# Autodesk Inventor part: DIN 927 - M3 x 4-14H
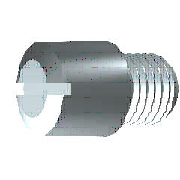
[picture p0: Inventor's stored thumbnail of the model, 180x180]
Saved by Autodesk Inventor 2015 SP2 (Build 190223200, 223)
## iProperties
IsCustomPart: 0
Created: 2012-02
Part Number: DIN 927 - M3 x 4-14H
Material: Stahl, weich
Description: Passschraube kopflos
Document SubType Name: Modeling
Standard: DIN 927
Designer: rYan
Standards Organization: DIN
Language: de-DE
Size Designation: M3 x 4-14H
Categories: <MemberInstance><Categories><Category DisplayName="Verbindungselemente" InternalName="e4da775c-781d-43d5-af7c-5136215cf5a6" Mnemonic="FSTN"><Category DisplayNam
Density: 7.85 g/cm^3
Mass: 0.616547 g
Surface Area: 1.17401 cm^2
Volume: 0.0785411 cm^3
Appearance: Halbpoliert
Author: rYan
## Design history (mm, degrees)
body "Solid1"
sketch "Skizze1"
  geometry: L1 (0, 0)-(8.5, 0); L2 (8.5, 0)-(8.5, 1.5); L3 (8.5, 1.5)-(4, 1.5); L4 (4, 1.5)-(4, 2); L5 (4, 2)-(0, 2); L6 (0, 2)-(0, 0); L7 (-1.7, 0)-(10.2, 0) reference; L8 (0, -0.4)-(0, 2.4) reference; A1 r 0.5 centre (4.25, 1.933) between (4, 1.5) and (4.5, 1.5)
  constraints: 12 end point, 4 parallel, 2 collinear, 2 point on circle, 1 centre point, 1 horizontal, 1 perpendicular, 1 point on line
  dimensions: "d0" = 4 distance between parallel lines of L4 L6 (= KOH); "d1" = 4.5 distance between parallel lines of L2 L4 (= GEL); "d2" = 3 diameter of L3 L1 (= NND); "d3" = 4 diameter of L5 L1 (= KOD); "d14" = 0.5 distance of A1.end L3.end (= SBR); "d15" = 0.5 radius of A1 (= SBR)
revolve "Körper" stored, may be unused: angle "d4" = 90 deg
sketch "Skizze2"
  geometry: L1 (0, -2.8)-(0, 2.8) reference; L2 (-2.8, 0)-(2.8, 0) reference; L3 (-2, 0.25)-(2, 0.25); L4 (2, 0.25)-(2, -0.25); L5 (2, -0.25)-(-2, -0.25); L6 (-2, -0.25)-(-2, 0.25); L7 (-2, 0)-(2, 0); L8 (0, 0.25)-(0, -0.25); C1 r 2 at (0, 0) reference
  constraints: 12 end point, 4 midpoint, 2 collinear, 2 parallel, 1 horizontal, 1 perpendicular, 1 tangent
  dimensions: "d5" = 0.5 distance between parallel lines of L3 L5 (= SBR)
extrude "Loch" cut sketch "Skizze2" distance "d6" = 0.8 (= STI); taper "d7" = 0 deg
chamfer "Fase1" distance "d8" = 0.5 (= PHH); stored, may be unused: angle "d9" = 45 deg, second distance "d19" = 0.5 (= PHH)
feature "Gewinde" dims "d10" = 4.5 (= GEL), "d11" = 0
chamfer "Fase2" distance "d12" = 0.30673 (= -0.5 x GD1 + 0.5 x NND); stored, may be unused: second distance "d13" = 0.30673 (= GUL), angle "d20" = 45 deg
revolve "Nut1" stored, may be unused: angle "d16" = 90 deg
workplane "Work Plane1"
other parameters: "NND" = 3 [user parameter; used in 2 equation terms], "GEL" = 4.5 [user parameter; used in 3 equation terms], "KOD" = 4 [user parameter; used in 1 equation term], "KOH" = 4 [user parameter; used in 1 equation term], "SBR" = 0.5 [user parameter; used in 3 equation terms], "GUL" = 0.30673 (= 0.61345 x PTC) [user parameter; used in 1 equation term], "PHH" = 0.5 [user parameter; used in 2 equation terms], "GD1" = 2.38655 (= THREADDIA - 1.2269 x PTC) [user parameter; used in 1 equation term], "STI" = 0.8 [user parameter; used in 1 equation term], "d18" = 0, "d21" = 0, "d23" = 0, "THREADDIA" = 3 [user parameter; used in 1 equation term], "TOA" = 30 deg [user parameter], "NLG" = 4.5 (= GEL) [user parameter], "PTC" = 0.5 [user parameter; used in 4 equation terms], "GAL" = 0.30673 (= 0.61345 x PTC) [user parameter]
